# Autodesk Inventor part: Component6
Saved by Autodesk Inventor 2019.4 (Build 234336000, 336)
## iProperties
Created: 2020-04
Part Number: Component6
Material: Generic
Document SubType Name: Modeling
Designer: Administrator
Density: 1 g/cm^3
Appearance: Default
Title: Component6
Author: Administrator
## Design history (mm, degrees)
feature "Body1"
body "Solid1"
